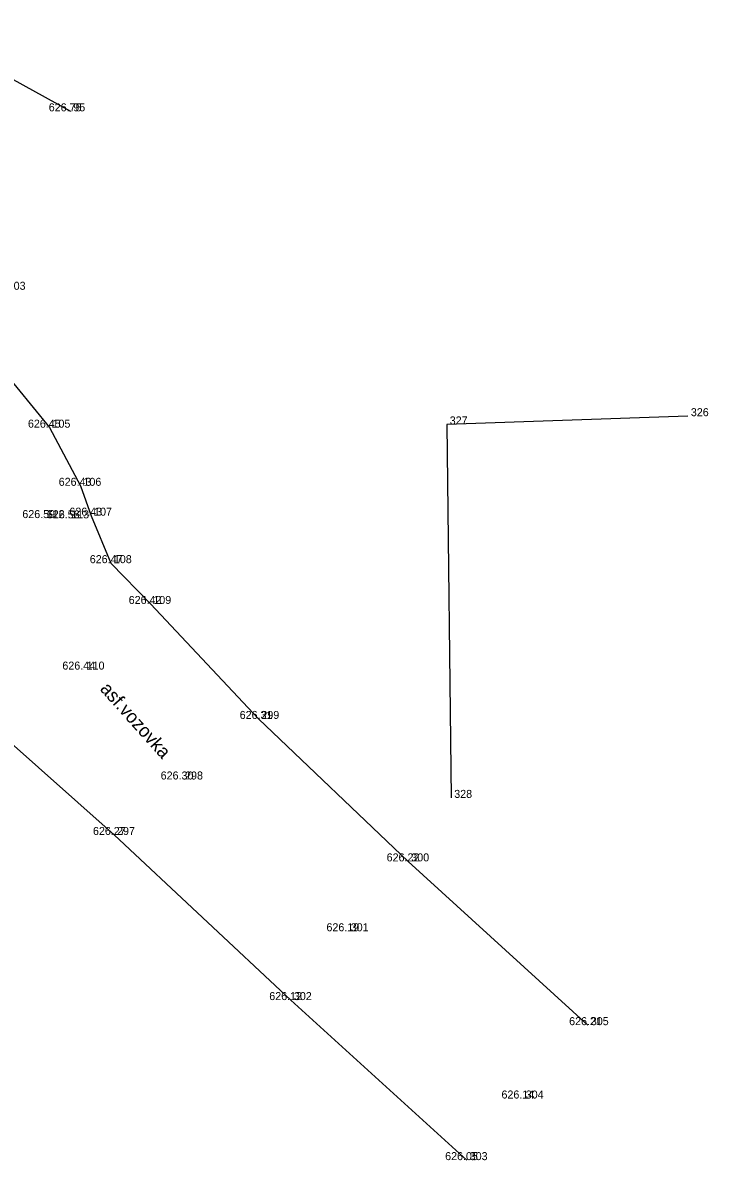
# Model space of a CAD drawing. Extents: x -632073 to -631949, y -1099530 to -1099406.
# Drawn here: x -631974.23 to -631948.54, y -1099529.71 to -1099487.07 of the extents above; entities that cross this region are included whole.
import ezdxf

# ---------------------------------------------------------------- set-up
doc = ezdxf.new("R2010")
doc.units = 0
for name, color, linetype in [('Vrstva 10', 7, 'Continuous'), ('Vrstva 13', 7, 'Continuous'), ('Vrstva 14', 7, 'Continuous'), ('Vrstva 15', 7, 'Continuous'), ('Vrstva 22', 7, 'Continuous'), ('Vrstva 5', 7, 'Continuous'), ('Vrstva 8', 7, 'Continuous')]:
    doc.layers.add(name, color=color, linetype=linetype)

msp = doc.modelspace()

# ---------------------------------------------------------------- linework, layer by layer
at = {"layer": 'Vrstva 10'}
for p, q in [((-631949.3, -1099501.82), (-631958.34, -1099502.13)), ((-631958.34, -1099502.13), (-631958.17, -1099516.13))]:
    msp.add_line(p, q, dxfattribs=at)
at = {"layer": 'Vrstva 13'}
for p, q in [((-631972.45, -1099490.39), (-631972.45, -1099490.39)), ((-631949.3, -1099501.82), (-631949.3, -1099501.82)), ((-631973.23, -1099502.25), (-631973.23, -1099502.25)), ((-631958.34, -1099502.13), (-631958.34, -1099502.13)), ((-631972.07, -1099504.43), (-631972.07, -1099504.43)), ((-631973.45, -1099505.64), (-631973.45, -1099505.64)), ((-631972.53, -1099505.65), (-631972.53, -1099505.65)), ((-631971.67, -1099505.55), (-631971.67, -1099505.55)), ((-631970.93, -1099507.33), (-631970.93, -1099507.33)), ((-631969.45, -1099508.86), (-631969.45, -1099508.86)), ((-631971.95, -1099511.32), (-631971.95, -1099511.32)), ((-631965.4, -1099513.17), (-631965.4, -1099513.17)), ((-631968.26, -1099515.44), (-631968.26, -1099515.44)), ((-631958.17, -1099516.13), (-631958.17, -1099516.13)), ((-631970.81, -1099517.52), (-631970.81, -1099517.52)), ((-631959.78, -1099518.51), (-631959.78, -1099518.51)), ((-631962.05, -1099521.13), (-631962.05, -1099521.13)), ((-631964.18, -1099523.71), (-631964.18, -1099523.71)), ((-631953.05, -1099524.65), (-631953.05, -1099524.65)), ((-631955.49, -1099527.4), (-631955.49, -1099527.4)), ((-631957.59, -1099529.71), (-631957.59, -1099529.71))]:
    msp.add_line(p, q, dxfattribs=at)
at = {"layer": 'Vrstva 5'}
msp.add_line((-631978.43, -1099487.07), (-631972.45, -1099490.39), dxfattribs=at)
at = {"layer": 'Vrstva 8'}
for p, q in [((-631975.07, -1099500), (-631973.23, -1099502.25)), ((-631973.23, -1099502.25), (-631972.07, -1099504.43)), ((-631972.07, -1099504.43), (-631971.67, -1099505.55)), ((-631971.67, -1099505.55), (-631970.93, -1099507.33)), ((-631970.93, -1099507.33), (-631969.45, -1099508.86)), ((-631969.45, -1099508.86), (-631965.4, -1099513.17)), ((-631965.4, -1099513.17), (-631959.78, -1099518.51)), ((-631975, -1099513.78), (-631970.81, -1099517.52)), ((-631970.81, -1099517.52), (-631964.18, -1099523.71)), ((-631959.78, -1099518.51), (-631953.05, -1099524.65)), ((-631964.18, -1099523.71), (-631957.59, -1099529.71))]:
    msp.add_line(p, q, dxfattribs=at)

# ---------------------------------------------------------------- texts
at = {"layer": 'Vrstva 14'}
for s, p in [(' 95', (-631972.45, -1099490.39)), (' 103', (-631974.91, -1099497.08)), (' 326', (-631949.3, -1099501.82)), (' 105', (-631973.23, -1099502.25)), (' 327', (-631958.34, -1099502.13)), (' 106', (-631972.07, -1099504.43)), (' 112', (-631973.45, -1099505.64)), (' 113', (-631972.53, -1099505.65)), (' 107', (-631971.67, -1099505.55)), (' 108', (-631970.93, -1099507.33)), (' 109', (-631969.45, -1099508.86)), (' 110', (-631971.95, -1099511.32)), (' 299', (-631965.4, -1099513.17)), (' 298', (-631968.26, -1099515.44)), (' 328', (-631958.17, -1099516.13)), (' 297', (-631970.81, -1099517.52)), (' 300', (-631959.78, -1099518.51)), (' 301', (-631962.05, -1099521.13)), (' 302', (-631964.18, -1099523.71)), (' 305', (-631953.05, -1099524.65)), (' 304', (-631955.49, -1099527.4)), (' 303', (-631957.59, -1099529.71))]:
    msp.add_text(s, height=0.3, dxfattribs=at).set_placement(p)
at = {"layer": 'Vrstva 15'}
for s, p in [('626.75 ', (-631973.26, -1099490.39)), ('626.45 ', (-631974.04, -1099502.25)), ('626.43 ', (-631972.887, -1099504.43)), ('626.59 ', (-631974.25, -1099505.64)), ('626.56 ', (-631973.33, -1099505.65)), ('626.43 ', (-631972.487, -1099505.55)), ('626.47 ', (-631971.722, -1099507.33)), ('626.42 ', (-631970.263, -1099508.86)), ('626.44 ', (-631972.749, -1099511.32)), ('626.31 ', (-631966.102, -1099513.17)), ('626.30 ', (-631969.064, -1099515.44)), ('626.27 ', (-631971.602, -1099517.52)), ('626.22 ', (-631960.593, -1099518.51)), ('626.19 ', (-631962.849, -1099521.13)), ('626.12 ', (-631964.993, -1099523.71)), ('626.21 ', (-631953.752, -1099524.65)), ('626.14 ', (-631956.288, -1099527.4)), ('626.05 ', (-631958.4, -1099529.71))]:
    msp.add_text(s, height=0.3, dxfattribs=at).set_placement(p)
at = {"layer": 'Vrstva 22'}
msp.add_text('asf.vozovka', height=0.5, rotation=311.8486, dxfattribs=at).set_placement((-631971.365, -1099512.066))

doc.saveas('drawing.dxf')
